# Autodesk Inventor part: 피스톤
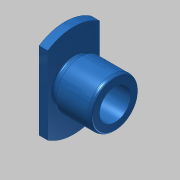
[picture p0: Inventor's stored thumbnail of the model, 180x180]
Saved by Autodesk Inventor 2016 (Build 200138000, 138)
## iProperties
Created: 2019-02
Part Number: 피스톤
Material: 알루미늄 6061
Document SubType Name: Modeling
Designer: mduedu
Density: 1 g/cm^3
Appearance: 청록색
Author: mduedu
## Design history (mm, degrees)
sketch "스케치1"
  geometry: C1 r 27 at (0, 0); 1 further point
  constraints: 1 centre point, 1 coincident
  dimensions: "d0" = 54 diameter of C1
extrude "돌출1" new body sketch "스케치1" distance "d1" = 5; taper "d2" = 0 deg
sketch "스케치2"
  geometry: L1 (-15, -27)-(15, -27); L2 (15, -27)-(15, 27); L3 (15, 27)-(-15, 27); L4 (-15, 27)-(-15, -27); L5 (-15, -27)-(15, 27); L6 (15, -27)-(-15, 27); C1 r 27 at (0, 0) reference; 1 further point
  constraints: 12 end point, 2 midpoint, 2 parallel, 1 horizontal, 1 perpendicular, 1 tangent
  dimensions: "d3" = 30 distance of L2.end L3.end
extrude "돌출2" sketch "스케치2" stored distance "d5" = 5; taper "d6" = 0 deg
sketch "스케치3"
  geometry: C1 r 12 at (0, 0); 1 further point
  constraints: 1 centre point, 1 coincident
  dimensions: "d7" = 24 diameter of C1
extrude "돌출3" join sketch "스케치3" distance "d8" = 4; taper "d9" = 0 deg
sketch "스케치4"
  geometry: C1 r 14 at (0, 0); 1 further point
  constraints: 1 centre point, 1 coincident
  dimensions: "d10" = 28 diameter of C1
extrude "돌출4" join sketch "스케치4" distance "d11" = 20; taper "d12" = 0 deg
fillet "모깎기1" dims "d13" = 1
chamfer "모따기1" distance "d14" = 1.8; stored, may be unused: second distance "d15" = 2, angle "d16" = 15 deg
fillet "모깎기2" dims "d17" = 1, "d18" = 2
sketch "스케치5"
  geometry: 2 further points
  constraints: 1 coincident
hole "구멍1" sketch "스케치5" at (0, 0) diameter "d19" = 18; stored, may be unused: countersink angle "d23" = 90 deg, drill point angle "d25" = 118 deg; dims "d20" = 6, "d21" = 4, "d22" = 2, "d24" = 15
node "솔리드1"
